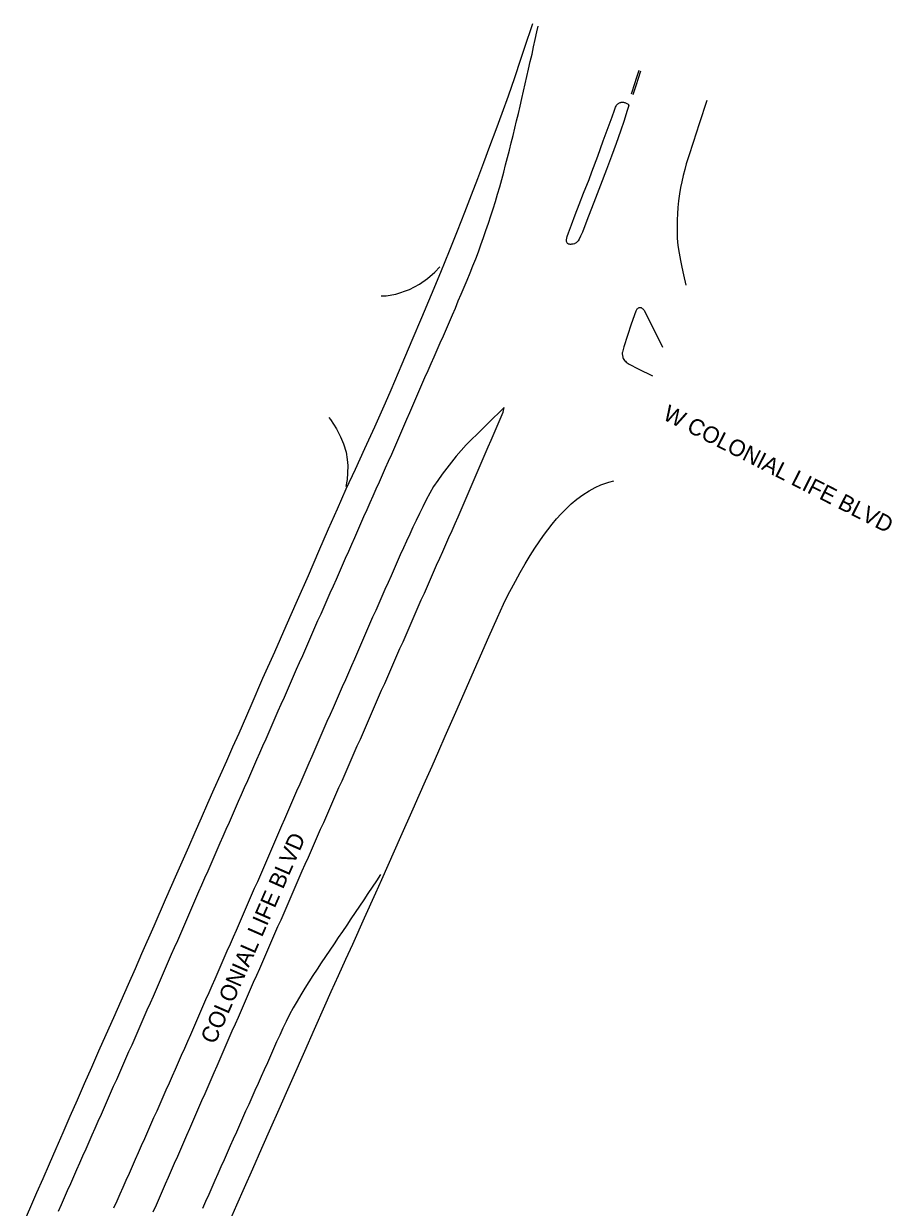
# Model space of a CAD drawing. Extents: x 1948091 to 1975253, y 787267 to 823306.
# Drawn here: x 1971602.8 to 1971888.8, y 796247.2 to 796637.1 of the extents above; entities that cross this region are included whole.
import ezdxf

# ---------------------------------------------------------------- set-up
doc = ezdxf.new("R2010")
doc.units = 0
for name, color, linetype in [('RD_EX_Conc', 7, 'Continuous'), ('RD_EX_Pavement_Markings', 7, 'Continuous'), ('RD_EX_Road', 7, 'Continuous'), ('RD_TX_RoadID', 7, 'Continuous')]:
    doc.layers.add(name, color=color, linetype=linetype)

msp = doc.modelspace()

# ---------------------------------------------------------------- linework, layer by layer
at = {"layer": 'RD_EX_Conc'}
for points in [[(1971720.55, 796547.42), (1971722.15, 796547.49), (1971725.38, 796548.02), (1971729.81, 796549.51), (1971733.12, 796551.26), (1971735.75, 796553.1), (1971738.18, 796555.28), (1971739.78, 796557)], [(1971813.3, 796530.46), (1971811.45, 796534.09), (1971808.8, 796539.44), (1971807.3, 796542.39), (1971807.14, 796542.61), (1971806.97, 796542.83), (1971806.78, 796543.02), (1971806.58, 796543.2), (1971806.38, 796543.35), (1971806.19, 796543.46), (1971806.02, 796543.52), (1971805.86, 796543.54), (1971805.72, 796543.54), (1971805.57, 796543.52), (1971805.44, 796543.48), (1971805.31, 796543.44), (1971805.18, 796543.37), (1971805.04, 796543.28), (1971804.9, 796543.15), (1971804.74, 796543), (1971804.59, 796542.81), (1971804.45, 796542.6), (1971804.33, 796542.35), (1971802.87, 796538.06), (1971800.46, 796530.63), (1971799.92, 796528.87), (1971799.9, 796528.71), (1971799.9, 796528.28), (1971799.96, 796527.73), (1971800.06, 796527.25), (1971800.13, 796527.04), (1971800.21, 796526.85), (1971800.41, 796526.49), (1971800.67, 796526.15), (1971800.91, 796525.87), (1971801.17, 796525.63), (1971802.17, 796524.92), (1971805.13, 796523.39), (1971809.86, 796521.08)], [(1971703.23, 796507.35), (1971703.83, 796506.71), (1971705.76, 796503.68), (1971707.1, 796501.03), (1971708.06, 796498.7), (1971709, 796495.92), (1971709.32, 796493.58), (1971709.5, 796491.52), (1971709.38, 796489.04), (1971709.27, 796486.89), (1971708.83, 796484.59)]]:
    msp.add_lwpolyline(points, dxfattribs=at)
at = {"layer": 'RD_EX_Pavement_Markings'}
for points in [[(1971614.22, 796245.89), (1971615.23, 796248.18), (1971616.24, 796250.47), (1971617.25, 796252.75), (1971618.26, 796255.04), (1971619.27, 796257.33), (1971620.28, 796259.61), (1971621.29, 796261.9), (1971622.3, 796264.19), (1971623.31, 796266.47), (1971624.32, 796268.76), (1971625.33, 796271.05), (1971626.34, 796273.33), (1971627.35, 796275.62), (1971628.36, 796277.91), (1971629.37, 796280.2), (1971630.38, 796282.48), (1971631.39, 796284.77), (1971632.4, 796287.06), (1971633.41, 796289.34), (1971634.42, 796291.63), (1971635.43, 796293.92), (1971636.44, 796296.21), (1971637.44, 796298.49), (1971638.45, 796300.78), (1971639.46, 796303.07), (1971640.47, 796305.36), (1971641.47, 796307.65), (1971642.48, 796309.93), (1971643.49, 796312.22), (1971644.5, 796314.51), (1971645.5, 796316.8), (1971646.49, 796319.09), (1971647.49, 796321.39), (1971648.49, 796323.68), (1971649.49, 796325.97), (1971650.49, 796328.26), (1971651.49, 796330.55), (1971652.49, 796332.84), (1971653.49, 796335.13), (1971654.49, 796337.43), (1971655.48, 796339.72), (1971656.48, 796342.01), (1971657.48, 796344.31), (1971658.47, 796346.6), (1971659.47, 796348.89), (1971660.47, 796351.18), (1971661.48, 796353.47), (1971662.48, 796355.76), (1971663.48, 796358.05), (1971664.48, 796360.34), (1971665.48, 796362.63), (1971666.49, 796364.92), (1971667.49, 796367.21), (1971668.49, 796369.5), (1971669.5, 796371.79), (1971670.5, 796374.08), (1971671.5, 796376.37), (1971672.51, 796378.66), (1971673.52, 796380.95), (1971674.53, 796383.23), (1971675.54, 796385.52), (1971676.54, 796387.81), (1971677.55, 796390.1), (1971678.56, 796392.39), (1971679.57, 796394.67), (1971680.57, 796396.96), (1971681.58, 796399.25), (1971682.59, 796401.54), (1971683.59, 796403.83), (1971684.6, 796406.11), (1971685.61, 796408.4), (1971686.61, 796410.69), (1971687.62, 796412.98), (1971688.63, 796415.27), (1971689.63, 796417.56), (1971690.64, 796419.84), (1971691.64, 796422.13), (1971692.65, 796424.42), (1971693.65, 796426.71), (1971694.66, 796429), (1971695.66, 796431.29), (1971696.67, 796433.58), (1971697.67, 796435.87), (1971698.67, 796438.16), (1971699.68, 796440.45), (1971700.7, 796442.73), (1971701.71, 796445.02), (1971702.72, 796447.3), (1971703.74, 796449.59), (1971704.75, 796451.87), (1971705.77, 796454.16), (1971706.78, 796456.44), (1971707.79, 796458.73), (1971708.8, 796461.01), (1971709.81, 796463.3), (1971710.82, 796465.59), (1971711.82, 796467.88), (1971712.83, 796470.17), (1971713.84, 796472.45), (1971714.84, 796474.74), (1971715.85, 796477.03), (1971716.86, 796479.32), (1971717.87, 796481.6), (1971718.89, 796483.89), (1971719.91, 796486.17), (1971720.92, 796488.45), (1971721.94, 796490.74), (1971722.95, 796493.02), (1971723.97, 796495.31), (1971724.99, 796497.59), (1971726, 796499.88), (1971726.99, 796502.17), (1971727.98, 796504.46), (1971728.97, 796506.76), (1971729.97, 796509.05), (1971730.96, 796511.35), (1971731.95, 796513.64), (1971732.94, 796515.94), (1971733.94, 796518.23), (1971734.93, 796520.52), (1971735.94, 796522.81), (1971736.95, 796525.1), (1971737.96, 796527.39), (1971738.96, 796529.68), (1971739.97, 796531.96), (1971740.98, 796534.25), (1971741.98, 796536.54), (1971742.99, 796538.83), (1971743.96, 796541.13), (1971744.93, 796543.43), (1971745.91, 796545.74), (1971746.88, 796548.04), (1971747.85, 796550.34), (1971748.83, 796552.65), (1971749.76, 796554.96), (1971750.69, 796557.28), (1971751.63, 796559.6), (1971752.54, 796561.93), (1971753.37, 796564.29), (1971754.19, 796566.65), (1971755.01, 796569.01), (1971755.84, 796571.37), (1971756.64, 796573.74), (1971757.38, 796576.12), (1971758.12, 796578.51), (1971758.85, 796580.9), (1971759.55, 796583.3), (1971760.19, 796585.72), (1971760.84, 796588.13), (1971761.48, 796590.55), (1971762.13, 796592.96), (1971762.77, 796595.38), (1971763.36, 796597.81), (1971763.94, 796600.24), (1971764.52, 796602.67), (1971765.1, 796605.1), (1971765.69, 796607.53), (1971766.27, 796609.96), (1971766.85, 796612.39), (1971767.41, 796614.83), (1971767.96, 796617.27), (1971768.51, 796619.71), (1971769.07, 796622.14), (1971769.62, 796624.58), (1971770.18, 796627.02), (1971770.7, 796629.46), (1971771.23, 796631.91), (1971771.75, 796634.35), (1971772.17, 796636.26)], [(1971805.33, 796621.68), (1971804.57, 796619.3), (1971803.81, 796616.91), (1971803.04, 796614.53), (1971802.82, 796613.84)], [(1971805.93, 796621.41), (1971805.14, 796619.04), (1971804.38, 796616.66), (1971803.62, 796614.28), (1971803.42, 796613.65)], [(1971645.45, 796245.74), (1971646.46, 796248.03), (1971647.47, 796250.32), (1971648.47, 796252.61), (1971649.48, 796254.9), (1971650.48, 796257.19), (1971651.49, 796259.47), (1971652.49, 796261.76), (1971653.5, 796264.05), (1971654.51, 796266.34), (1971655.51, 796268.63), (1971656.51, 796270.92), (1971657.51, 796273.21), (1971658.5, 796275.51), (1971659.5, 796277.8), (1971660.5, 796280.09), (1971661.49, 796282.39), (1971662.49, 796284.68), (1971663.48, 796286.97), (1971664.48, 796289.27), (1971665.48, 796291.56), (1971666.47, 796293.85), (1971667.47, 796296.14), (1971668.47, 796298.43), (1971669.47, 796300.72), (1971670.48, 796303.01), (1971671.48, 796305.3), (1971672.49, 796307.59), (1971673.49, 796309.88), (1971674.49, 796312.17), (1971675.5, 796314.46), (1971676.5, 796316.75), (1971677.51, 796319.04), (1971678.51, 796321.33), (1971679.51, 796323.62), (1971680.52, 796325.91), (1971681.52, 796328.2), (1971682.52, 796330.49), (1971683.52, 796332.78), (1971684.52, 796335.07), (1971685.52, 796337.37), (1971686.52, 796339.66), (1971687.52, 796341.95), (1971688.51, 796344.24), (1971689.51, 796346.53), (1971690.51, 796348.82), (1971691.51, 796351.12), (1971692.51, 796353.41), (1971693.51, 796355.7), (1971694.51, 796357.99), (1971695.52, 796360.28), (1971696.53, 796362.56), (1971697.54, 796364.85), (1971698.55, 796367.14), (1971699.55, 796369.43), (1971700.56, 796371.71), (1971701.57, 796374), (1971702.58, 796376.29), (1971703.59, 796378.58), (1971704.6, 796380.87), (1971705.6, 796383.15), (1971706.61, 796385.44), (1971707.61, 796387.73), (1971708.62, 796390.02), (1971709.62, 796392.31), (1971710.63, 796394.6), (1971711.64, 796396.89), (1971712.64, 796399.18), (1971713.65, 796401.46), (1971714.65, 796403.75), (1971715.65, 796406.04), (1971716.65, 796408.34), (1971717.65, 796410.63), (1971718.66, 796412.92), (1971719.66, 796415.21), (1971720.66, 796417.5), (1971721.66, 796419.79), (1971722.66, 796422.08), (1971723.67, 796424.37), (1971724.67, 796426.66), (1971725.68, 796428.95), (1971726.68, 796431.23), (1971727.69, 796433.52), (1971728.69, 796435.81), (1971729.7, 796438.1), (1971730.7, 796440.39), (1971731.71, 796442.68), (1971732.71, 796444.97), (1971733.72, 796447.26), (1971734.72, 796449.54), (1971735.73, 796451.83), (1971736.75, 796454.12), (1971737.76, 796456.4), (1971738.77, 796458.69), (1971739.78, 796460.98), (1971740.79, 796463.26), (1971741.81, 796465.55), (1971742.82, 796467.83), (1971743.83, 796470.12), (1971744.84, 796472.4), (1971745.86, 796474.69), (1971746.87, 796476.98), (1971747.85, 796479.27), (1971748.84, 796481.57), (1971749.82, 796483.87), (1971750.81, 796486.17), (1971751.79, 796488.46), (1971752.78, 796490.76), (1971753.77, 796493.06), (1971754.75, 796495.36), (1971755.74, 796497.65), (1971756.72, 796499.95), (1971757.71, 796502.25), (1971758.7, 796504.54), (1971759.68, 796506.84), (1971760.67, 796509.14), (1971760.98, 796510.62), (1971759.2, 796508.87), (1971757.41, 796507.12), (1971755.63, 796505.36), (1971753.85, 796503.61), (1971752.07, 796501.86), (1971750.29, 796500.1), (1971748.52, 796498.34), (1971746.81, 796496.51), (1971745.22, 796494.58), (1971743.63, 796492.65), (1971742.08, 796490.69), (1971740.57, 796488.7), (1971739.13, 796486.66), (1971737.74, 796484.58), (1971736.51, 796482.41), (1971735.31, 796480.21), (1971734.17, 796477.99), (1971733.08, 796475.74), (1971732.02, 796473.47), (1971730.97, 796471.21), (1971729.91, 796468.94), (1971728.87, 796466.67), (1971727.82, 796464.4), (1971726.79, 796462.12), (1971725.78, 796459.83), (1971724.78, 796457.54), (1971723.77, 796455.26), (1971722.76, 796452.97), (1971721.74, 796450.68), (1971720.73, 796448.4), (1971719.71, 796446.12), (1971718.69, 796443.84), (1971717.67, 796441.55), (1971716.65, 796439.27), (1971715.63, 796436.99), (1971714.63, 796434.69), (1971713.65, 796432.4), (1971712.66, 796430.1), (1971711.68, 796427.8), (1971710.69, 796425.51), (1971709.7, 796423.21), (1971708.71, 796420.91), (1971707.71, 796418.62), (1971706.7, 796416.34), (1971705.68, 796414.05), (1971704.67, 796411.77), (1971703.65, 796409.48), (1971702.64, 796407.2), (1971701.63, 796404.91), (1971700.62, 796402.63), (1971699.62, 796400.33), (1971698.63, 796398.04), (1971697.64, 796395.75), (1971696.64, 796393.45), (1971695.65, 796391.16), (1971694.65, 796388.86), (1971693.66, 796386.57), (1971692.66, 796384.28), (1971691.67, 796381.98), (1971690.67, 796379.69), (1971689.67, 796377.4), (1971688.68, 796375.11), (1971687.68, 796372.81), (1971686.69, 796370.52), (1971685.69, 796368.23), (1971684.7, 796365.93), (1971683.7, 796363.64), (1971682.71, 796361.34), (1971681.72, 796359.05), (1971680.72, 796356.76), (1971679.73, 796354.46), (1971678.73, 796352.17), (1971677.74, 796349.88), (1971676.74, 796347.58), (1971675.74, 796345.29), (1971674.73, 796343), (1971673.73, 796340.71), (1971672.73, 796338.43), (1971671.72, 796336.14), (1971670.72, 796333.85), (1971669.71, 796331.56), (1971668.71, 796329.27), (1971667.71, 796326.98), (1971666.7, 796324.69), (1971665.7, 796322.4), (1971664.7, 796320.11), (1971663.7, 796317.82), (1971662.7, 796315.52), (1971661.7, 796313.23), (1971660.7, 796310.94), (1971659.7, 796308.65), (1971658.69, 796306.36), (1971657.69, 796304.07), (1971656.69, 796301.78), (1971655.69, 796299.49), (1971654.68, 796297.2), (1971653.66, 796294.92), (1971652.65, 796292.63), (1971651.64, 796290.35), (1971650.63, 796288.06), (1971649.62, 796285.77), (1971648.6, 796283.49), (1971647.59, 796281.2), (1971646.58, 796278.92), (1971645.57, 796276.63), (1971644.55, 796274.34), (1971643.54, 796272.06), (1971642.53, 796269.77), (1971641.51, 796267.49), (1971640.5, 796265.2), (1971639.49, 796262.92), (1971638.47, 796260.63), (1971637.46, 796258.35), (1971636.44, 796256.06), (1971635.43, 796253.78), (1971634.41, 796251.49), (1971633.4, 796249.21), (1971632.38, 796246.93)], [(1971720.31, 796356.79), (1971718.92, 796354.72), (1971717.53, 796352.64), (1971716.13, 796350.56), (1971714.74, 796348.49), (1971713.35, 796346.41), (1971711.96, 796344.33), (1971710.56, 796342.26), (1971709.17, 796340.18), (1971707.78, 796338.11), (1971706.38, 796336.03), (1971704.98, 796333.96), (1971703.58, 796331.89), (1971702.18, 796329.82), (1971700.78, 796327.75), (1971699.38, 796325.68), (1971697.98, 796323.61), (1971696.65, 796321.49), (1971695.34, 796319.36), (1971694.04, 796317.23), (1971692.8, 796315.06), (1971691.56, 796312.89), (1971690.35, 796310.7), (1971689.26, 796308.45), (1971688.16, 796306.2), (1971687.08, 796303.95), (1971686.07, 796301.66), (1971685.05, 796299.38), (1971684.04, 796297.09), (1971683.02, 796294.81), (1971682, 796292.53), (1971680.97, 796290.25), (1971679.95, 796287.96), (1971678.93, 796285.68), (1971677.91, 796283.4), (1971676.89, 796281.12), (1971675.87, 796278.84), (1971674.84, 796276.56), (1971673.83, 796274.27), (1971672.82, 796271.99), (1971671.8, 796269.7), (1971670.79, 796267.41), (1971669.78, 796265.13), (1971668.76, 796262.84), (1971667.75, 796260.56), (1971666.74, 796258.27), (1971665.72, 796255.99), (1971664.71, 796253.7), (1971663.7, 796251.42), (1971662.68, 796249.13), (1971661.67, 796246.85)]]:
    msp.add_lwpolyline(points, dxfattribs=at)
at = {"layer": 'RD_EX_Road'}
for points in [[(1971770.3, 796637.08), (1971769.64, 796635.06), (1971768.26, 796630.86), (1971766.42, 796625.33), (1971764.38, 796619.28), (1971762.28, 796613.19), (1971760.24, 796607.54), (1971758.23, 796602.11), (1971756.21, 796596.67), (1971754.19, 796591.28), (1971752.2, 796585.99), (1971750.15, 796580.59), (1971747.92, 796574.89), (1971745.5, 796568.78), (1971742.88, 796562.14), (1971740.04, 796555.09), (1971736.98, 796547.74), (1971733.8, 796540.23), (1971730.62, 796532.72), (1971727.28, 796524.88), (1971723.63, 796516.41), (1971721.77, 796512.13), (1971718.26, 796504.19), (1971715.02, 796497.02), (1971711.91, 796490.23), (1971708.9, 796483.71), (1971705.98, 796477.21), (1971703.07, 796470.58), (1971699.9, 796463.27), (1971696.42, 796455.26), (1971692.83, 796447.03), (1971689.14, 796438.66), (1971685.34, 796430.1), (1971681.46, 796421.35), (1971677.54, 796412.42), (1971673.58, 796403.32), (1971671.57, 796398.74), (1971669.54, 796394.15), (1971667.48, 796389.54), (1971665.41, 796384.89), (1971663.33, 796380.19), (1971661.24, 796375.44), (1971659.14, 796370.63), (1971657.07, 796365.88), (1971653.13, 796356.89), (1971649.41, 796348.45), (1971645.6, 796339.79), (1971641.62, 796330.7), (1971639.46, 796325.79), (1971637.18, 796320.6), (1971634.76, 796315.14), (1971632.3, 796309.57), (1971629.86, 796304.07), (1971627.45, 796298.62), (1971625.08, 796293.24), (1971622.71, 796287.88), (1971620.36, 796282.51), (1971618, 796277.13), (1971615.65, 796271.74), (1971613.35, 796266.47), (1971611.14, 796261.42), (1971609.04, 796256.61), (1971607.03, 796252.02), (1971604.98, 796247.37), (1971602.77, 796242.34)], [(1971827.77, 796611.8), (1971825.24, 796604.12), (1971823.22, 796597.99), (1971821.77, 796593.53), (1971820.98, 796590.89), (1971820.5, 796589.07), (1971820, 796587.08), (1971819.53, 796585.04), (1971819.12, 796583.1), (1971818.77, 796581.07), (1971818.46, 796578.78), (1971818.23, 796576.48), (1971818.1, 796574.43), (1971818.02, 796572.52), (1971817.95, 796570.62), (1971817.93, 796568.62), (1971818.02, 796566.44), (1971818.23, 796564.07), (1971818.6, 796561.53), (1971819.05, 796559.04), (1971819.47, 796556.84), (1971820.02, 796554.34), (1971820.84, 796550.96)], [(1971670.62, 796242.8), (1971672.93, 796247.98), (1971675.46, 796253.68), (1971678.22, 796259.91), (1971681.19, 796266.66), (1971684.15, 796273.39), (1971686.86, 796279.52), (1971689.31, 796285.07), (1971691.51, 796290.02), (1971695.33, 796298.65), (1971698.53, 796305.9), (1971701.96, 796313.6), (1971704.08, 796318.3), (1971706.47, 796323.58), (1971708.9, 796328.94), (1971711.13, 796333.88), (1971715, 796342.51), (1971718.69, 796350.76), (1971720.7, 796355.22), (1971722.81, 796359.89), (1971724.94, 796364.64), (1971727.03, 796369.32), (1971731.05, 796378.45), (1971733.04, 796383.01), (1971735.11, 796387.71), (1971737.24, 796392.56), (1971739.45, 796397.55), (1971741.62, 796402.45), (1971745.52, 796411.3), (1971748.94, 796419.08), (1971752.45, 796427.05), (1971756, 796435.1), (1971758.82, 796441.46), (1971760.82, 796445.93), (1971762.29, 796449.03), (1971763.39, 796451.09), (1971764.71, 796453.47), (1971766.31, 796456.31), (1971767.97, 796459.16), (1971769.62, 796461.9), (1971771.14, 796464.33), (1971772.52, 796466.45), (1971773.91, 796468.45), (1971775.33, 796470.38), (1971776.76, 796472.21), (1971778.22, 796473.96), (1971779.75, 796475.66), (1971781.38, 796477.31), (1971783.09, 796478.9), (1971784.91, 796480.43), (1971786.87, 796481.87), (1971788.95, 796483.19), (1971790.93, 796484.29), (1971792.89, 796485.19), (1971795.49, 796486.09), (1971797.07, 796486.55)]]:
    msp.add_lwpolyline(points, dxfattribs=at)
msp.add_lwpolyline([(1971789.92, 796588.32), (1971791.82, 796593.41), (1971793.64, 796598.47), (1971795.23, 796602.86), (1971796.52, 796606.39), (1971797.33, 796608.61), (1971797.71, 796609.61), (1971797.87, 796609.95), (1971798.05, 796610.24), (1971798.23, 796610.47), (1971798.42, 796610.66), (1971798.61, 796610.82), (1971798.8, 796610.94), (1971798.98, 796611.03), (1971799.18, 796611.1), (1971799.38, 796611.16), (1971799.58, 796611.2), (1971799.8, 796611.23), (1971800.03, 796611.23), (1971800.26, 796611.22), (1971800.5, 796611.17), (1971800.75, 796611.11), (1971801.22, 796610.93), (1971801.43, 796610.81), (1971801.64, 796610.69), (1971801.81, 796610.55), (1971801.93, 796610.41), (1971802, 796610.26), (1971802.02, 796610.11), (1971801.95, 796609.78), (1971801.44, 796608.12), (1971800.48, 796605.22), (1971799.26, 796601.66), (1971797.85, 796597.61), (1971796.33, 796593.41), (1971794.71, 796589.03), (1971792.76, 796583.87), (1971790.56, 796578.15), (1971788.82, 796573.63), (1971787.61, 796570.53), (1971786.75, 796568.38), (1971786.18, 796567.05), (1971785.73, 796566.15), (1971785.35, 796565.6), (1971785, 796565.19), (1971784.84, 796565.02), (1971784.68, 796564.88), (1971784.5, 796564.77), (1971784.33, 796564.68), (1971784.14, 796564.61), (1971783.73, 796564.51), (1971783.23, 796564.43), (1971782.98, 796564.4), (1971782.75, 796564.39), (1971782.55, 796564.41), (1971782.38, 796564.44), (1971782.22, 796564.5), (1971782.06, 796564.6), (1971781.9, 796564.73), (1971781.74, 796564.89), (1971781.6, 796565.09), (1971781.51, 796565.31), (1971781.48, 796565.57), (1971781.51, 796565.85), (1971781.62, 796566.43), (1971781.77, 796566.96), (1971782.19, 796568.19), (1971783.15, 796570.83), (1971784.4, 796574.17), (1971785.7, 796577.49), (1971787.17, 796581.23), (1971788.96, 796585.81)], close=True, dxfattribs=at)

# ---------------------------------------------------------------- texts
at = {"layer": 'RD_TX_RoadID'}
for s, rotation, p in [('W COLONIAL LIFE BLVD', 333.054, (1971812.91, 796506.94)), ('COLONIAL LIFE BLVD', 66.3385, (1971665.76, 796300.66))]:
    msp.add_text(s, height=5.4, rotation=rotation, dxfattribs=at).set_placement(p)

doc.saveas('drawing.dxf')
